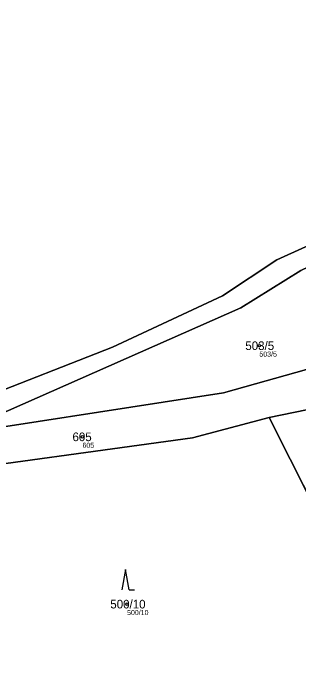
# Model space of a CAD drawing. Extents: x -766177 to -763254, y -1057727 to -1053915.
# Drawn here: x -765280 to -765223.6, y -1056436.7 to -1056306.7 of the extents above; entities that cross this region are included whole.
import ezdxf

# ---------------------------------------------------------------- set-up
doc = ezdxf.new("R2010")
doc.units = 0
for name, color, linetype in [('Vrstva 1', 7, 'Continuous'), ('Vrstva 2', 7, 'Continuous'), ('Vrstva 3', 7, 'Continuous'), ('Vrstva 50', 7, 'Continuous'), ('Vrstva 51', 7, 'Continuous')]:
    doc.layers.add(name, color=color, linetype=linetype)

msp = doc.modelspace()

# ---------------------------------------------------------------- linework, layer by layer
at = {"layer": 'Vrstva 1'}
for p, q in [((-765229.45, -1056386.41), (-765222.15, -1056384.87)), ((-765208.88, -1056427.15), (-765229.45, -1056386.41))]:
    msp.add_line(p, q, dxfattribs=at)
for points in [[(-765321.56, -1056374.82), (-765306.23, -1056384.88), (-765295.81, -1056385.68), (-765286.92, -1056382.87), (-765260.36, -1056372.5), (-765238.67, -1056362.41), (-765227.95, -1056355.32), (-765207.53, -1056346.09), (-765146.85, -1056327.24), (-765129.63, -1056323.56), (-765096.36, -1056318.28), (-765081.56, -1056314.03), (-765067.23, -1056307.39), (-765054.47, -1056309.45), (-765052.85, -1056313.32)], [(-765210.51, -1056351.35), (-765223.24, -1056357.44), (-765235.08, -1056364.75), (-765283.8, -1056386.26), (-765299.76, -1056390.99)], [(-765299.76, -1056390.99), (-765238.46, -1056381.53), (-765203.63, -1056371.77)], [(-765229.45, -1056386.41), (-765244.61, -1056390.39), (-765299.12, -1056397.88), (-765316.95, -1056394.87)]]:
    msp.add_lwpolyline(points, dxfattribs=at)
at = {"layer": 'Vrstva 3'}
for p, q in [((-765257.81, -1056416.35), (-765258.56, -1056420.35)), ((-765257.06, -1056420.35), (-765257.81, -1056416.35)), ((-765257.06, -1056420.35), (-765256.064, -1056420.35))]:
    msp.add_line(p, q, dxfattribs=at)
at = {"layer": 'Vrstva 50'}
for centre in [(-765231.41, -1056372.23994), (-765266.29, -1056390.18994), (-765257.5, -1056423.13994)]:
    msp.add_circle(centre, 0.25, dxfattribs=at)
at = {"layer": 'Vrstva 51'}
for points in [[(-765386.27, -1056249.12), (-765345.84, -1056307.83), (-765323.95, -1056348.38), (-765321.56, -1056374.82), (-765306.23, -1056384.88), (-765295.81, -1056385.68), (-765286.92, -1056382.87), (-765260.36, -1056372.5), (-765238.67, -1056362.41), (-765227.95, -1056355.32), (-765207.53, -1056346.09), (-765146.85, -1056327.24), (-765129.63, -1056323.56), (-765096.36, -1056318.28), (-765081.56, -1056314.03), (-765067.23, -1056307.39), (-765054.47, -1056309.45), (-765052.85, -1056313.32), (-765032.03, -1056299.11)], [(-765283.8, -1056386.26), (-765235.08, -1056364.75), (-765223.24, -1056357.44), (-765210.51, -1056351.35), (-765194.05, -1056345.3), (-765145.26, -1056331.5), (-765111.02, -1056324.6), (-765097.78, -1056321.93), (-765078.16, -1056315.76), (-765062.54, -1056311.78), (-765059.72, -1056313.43), (-765060.23, -1056318.36), (-765052.85, -1056313.32), (-765054.47, -1056309.45), (-765067.23, -1056307.39), (-765081.56, -1056314.03), (-765096.36, -1056318.28), (-765129.63, -1056323.56), (-765146.85, -1056327.24), (-765207.53, -1056346.09), (-765227.95, -1056355.32), (-765238.67, -1056362.41), (-765260.36, -1056372.5), (-765286.92, -1056382.87)], [(-765299.12, -1056397.88), (-765244.61, -1056390.39), (-765229.45, -1056386.41), (-765222.15, -1056384.87), (-765200.48, -1056380.28), (-765162.12, -1056383), (-765147.06, -1056384.69), (-765146.43, -1056385.08), (-765146.04, -1056385.32), (-765145.7, -1056385.54), (-765140.15, -1056387.86), (-765132.93, -1056390.85), (-765142.46, -1056382.09), (-765169.42, -1056376.81), (-765202.74, -1056374.45), (-765203.63, -1056371.77), (-765238.46, -1056381.53), (-765299.76, -1056390.99)]]:
    msp.add_lwpolyline(points, dxfattribs=at)
for points in [[(-765210.51, -1056351.35), (-765223.24, -1056357.44), (-765235.08, -1056364.75), (-765283.8, -1056386.26), (-765299.76, -1056390.99), (-765238.46, -1056381.53), (-765203.63, -1056371.77), (-765204.4, -1056369.49)], [(-765203.5, -1056422.21), (-765207.26, -1056413.6), (-765222.15, -1056384.87), (-765229.45, -1056386.41), (-765208.88, -1056427.15)], [(-765245.76, -1056449.78), (-765235.4, -1056443.62), (-765232.31, -1056448.66), (-765208.88, -1056427.15), (-765229.45, -1056386.41), (-765244.61, -1056390.39), (-765299.12, -1056397.88), (-765316.95, -1056394.87), (-765326.17, -1056404.67), (-765289, -1056461.31), (-765276.08, -1056479.61), (-765269.29, -1056474.33), (-765265.9, -1056479.49), (-765241.36, -1056456.97)]]:
    msp.add_lwpolyline(points, close=True, dxfattribs=at)

# ---------------------------------------------------------------- texts
at = {"layer": 'Vrstva 2'}
for s, p in [('503/5', (-765234.183, -1056373.09)), ('605', (-765268.264, -1056391.04)), ('500/10', (-765260.805, -1056423.99))]:
    msp.add_text(s, height=1.699998, dxfattribs=at).set_placement(p)
at = {"layer": 'Vrstva 50'}
for s, p in [('503/5', (-765231.41, -1056374.396)), ('605', (-765266.29, -1056392.346)), ('500/10', (-765257.5, -1056425.296))]:
    msp.add_text(s, height=0.999996, dxfattribs=at).set_placement(p)

doc.saveas('drawing.dxf')
